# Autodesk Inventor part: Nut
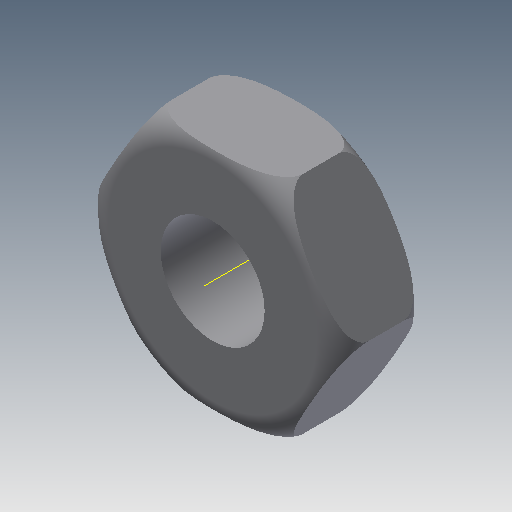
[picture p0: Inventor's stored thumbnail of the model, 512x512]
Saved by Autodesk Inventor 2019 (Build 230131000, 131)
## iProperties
Created: 2009-04
Part Number: Nut
Document SubType Name: Modeling
Designer: Sham
Density: 1 g/cm^3
Material: Generic
Appearance: Default
Mass: 4.65064 g
Surface Area: 21.3319 cm^2
Volume: 4.65064 cm^3
Author: Sham
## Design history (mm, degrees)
sketch "Sketch1"
  geometry: L1 (7.5, 12.99)-(15, 0); L2 (15, 0)-(7.5, -12.99); L3 (7.5, -12.99)-(-7.5, -12.99); L4 (-7.5, -12.99)-(-15, 0); L5 (-15, 0)-(-7.5, 12.99); L6 (-7.5, 12.99)-(7.5, 12.99); C1 r 6 at (0, 0); 1 further point
  constraints: 12 end point, 1 centre point, 1 coincident, 13 other
  dimensions: "d0" = 30 distance of L1.end L4.end; "d1" = 12 diameter of C1
extrude "Extrusion1" new body sketch "Sketch1" distance "d2" = 12; taper "d3" = 0 deg
sketch "Sketch2"
  geometry: L1 (-12, 0)-(-12, -0.022); L2 (-15, 7)-(-15, 3); L3 (0, -2.87)-(0, 12.87) reference; A1 r 3 centre (-12, 7) between (-12, 10) and (-15, 7); A2 r 3 centre (-12, 3) between (-15, 3) and (-12, 0)
  constraints: 4 end point, 4 point on circle, 2 centre point, 1 tangent
revolve "Revolution1" sketch "Sketch2" stored, may be unused: angle "d7" = 90 deg
body "Solid1"
other parameters: "d6" = 90 deg
